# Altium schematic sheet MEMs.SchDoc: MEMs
size A4; Date: Not used; ApprovedBy: Not used; CheckedBy: Not used; Author: Not used; CompanyName: STMicroelectronics; DrawnBy: Not used; Engineer: Not used; Organization: Not used; Address1: Not used; Address2: Not used; Address3: Not used; Address4: Not used; DocumentNumber: 12; Revision: Not used; SheetNumber: 12; SheetTotal: 16
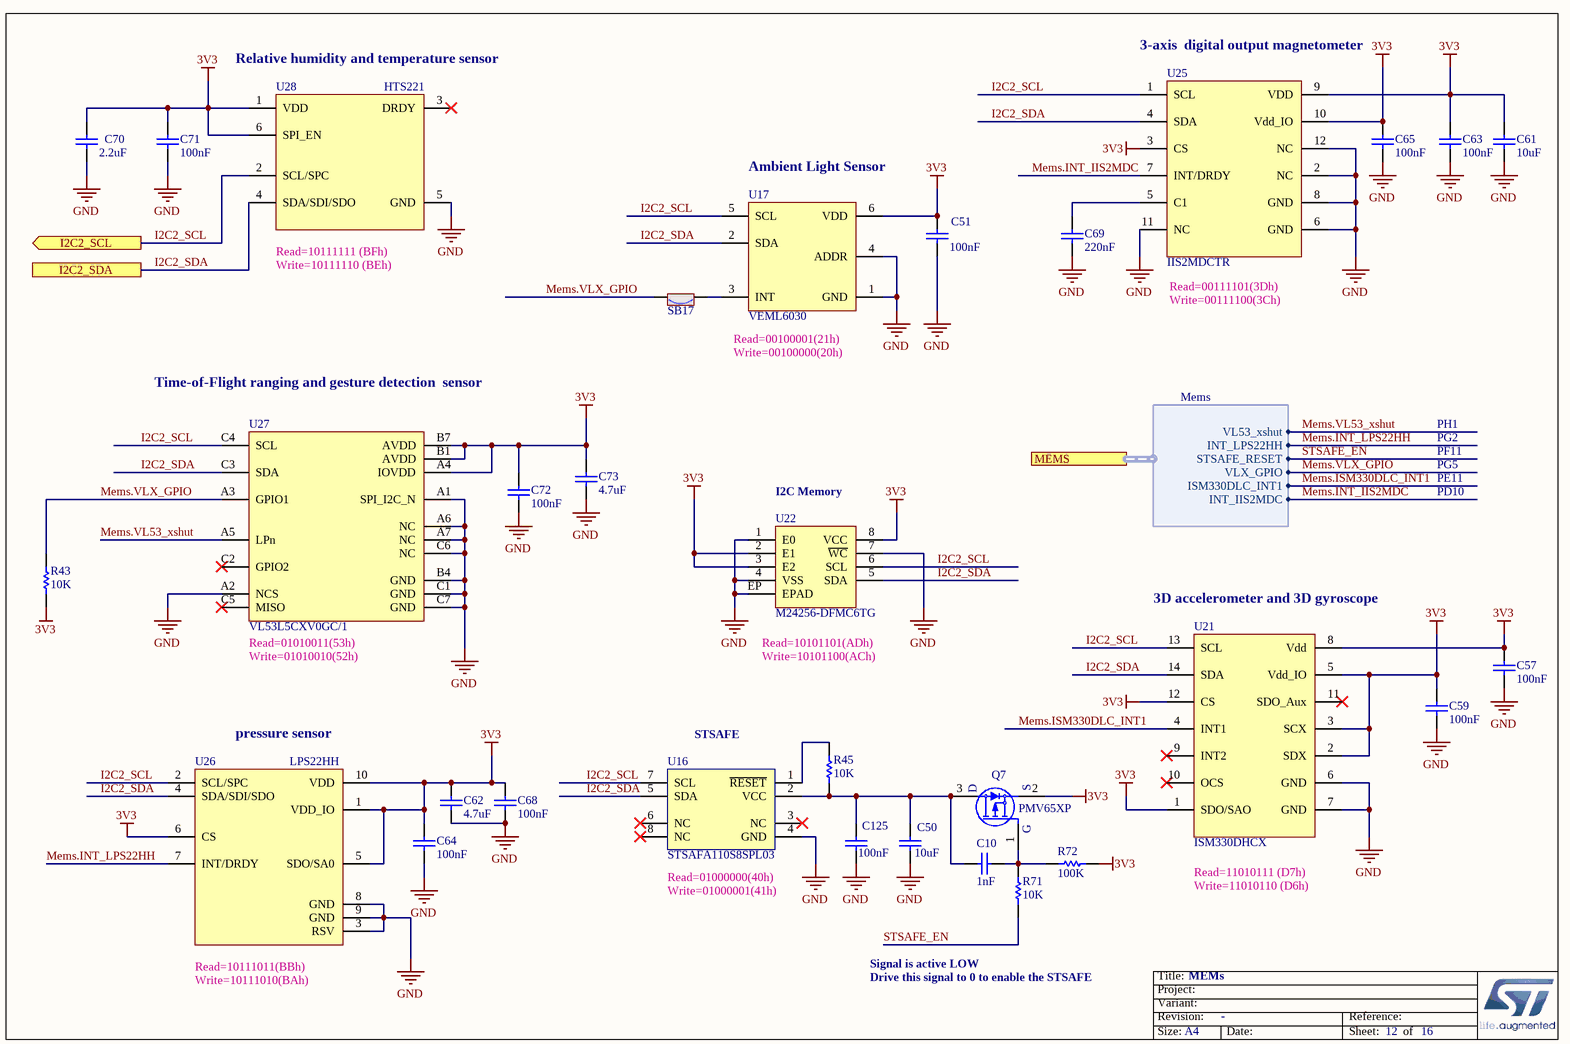
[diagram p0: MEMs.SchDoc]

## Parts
C10  value 1nF  [C0402]  (hidden comment: Capacitor)
C50  value 10uF  [C0402]  (hidden comment: Capacitor)
C51  value 100nF  [C0402]
C57  value 100nF  [C0402]
C59  value 100nF  [C0402]
C61  value 10uF  [C0603]  (hidden comment: Capacitor)
C62  value 4.7uF  [C0603]  (hidden comment: Capacitor)
C63  value 100nF  [C0402]
C64  value 100nF  [C0402]
C65  value 100nF  [C0402]
C68  value 100nF  [C0402]
C69  value 220nF  [C0402]  (hidden comment: Capacitor)
C70  value 2.2uF  [C0603_H0P8]  (hidden comment: Capacitor)
C71  value 100nF  [C0402]
C72  value 100nF  [C0402]
C73  value 4.7uF  [C0603]  (hidden comment: Capacitor)
C125  value 100nF  [C0402]
Q7  PMV65XP  [MOS_SOT23]
R43  value 10K  [R0402]  (hidden comment: Resistor)
R45  value 10K  [R0402]  (hidden comment: Resistor)
R71  value 10K  [R0402]  (hidden comment: Resistor)
R72  value 100K  [R0402]  (hidden comment: Resistor)
SB17  (no value)  [SOLDER-BRIDGE_R0603-0R]
U16  value STSAFA110S8SPL03  [ICC_SO8_5X4_P127]  (hidden comment: STSAFA110S8)
U17  VEML6030  [ICC_VISHAY_VEML6030_2X2_P065]
U21  ISM330DHCX  [ICC_LGA14_3X2P5_P050]
U22  value M24256-DFMC6TG  [ICC_DFN8-EPAD_2X3_P050]  (hidden comment: M24128-DFMC6TP)
U25  IIS2MDCTR  [ICC_LGA12_2X2_P050_H0P7]
U26  LPS22HH  [ICC_HLGA10_2X2_P050]
U27  value VL53L5CXV0GC/1  [ICC_LGA16_6P4X3_P075_H1P5]  (hidden comment: VL53L5CAV0GC)
U28  HTS221  [ICC_HLGA6_2X2_P075-1]

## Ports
I2C2_SCL (out), I2C2_SDA, MEMS (harness Mems)

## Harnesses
Mems: INT_LPS22HH, VLX_GPIO, ISM330DLC_INT1, INT_IIS2MDC, STSAFE_RESET, VL53_xshut

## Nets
3V3: C51.1 C57.1 C59.1 C61.2 C62.2 C63.1 C64.1 C65.1 C68.1 C70.2 C71.1 C72.1 C73.2 Q7.2(S) R43.2 R72.2 U17.6(VDD) U21.1(SDO/SAO) U21.2(SDX) U21.3(SCX) U21.5(Vdd_IO) U21.8(Vdd) U21.12(CS) U22.2(E1) U22.3(E2) U22.8(VCC) U25.3(CS) U25.9(VDD) U25.10(Vdd_IO) U26.1(VDD_IO) U26.5(SDO/SA0) U26.6(CS) U26.10(VDD) U27.A4(IOVDD) U27.B1(AVDD) U27.B7(AVDD) U28.1(VDD) U28.6(SPI_EN)
GND: C50.1 C51.2 C57.2 C59.2 C61.1 C62.1 C63.2 C64.2 C65.2 C68.2 C69.1 C70.1 C71.2 C72.2 C73.1 C125.2 U16.4(GND) U17.1(GND) U17.4(ADDR) U21.6(GND) U21.7(GND) U22.1(E0) U22.4(VSS) U22.7(~{WC}) U22.EP(EPAD) U25.2(NC) U25.6(GND) U25.8(GND) U25.11(NC) U25.12(NC) U26.3(RSV) U26.8(GND) U26.9(GND) U27.A1(SPI_I2C_N) U27.A2(NCS) U27.A6(NC) U27.A7(NC) U27.B4(GND) U27.C1(GND) U27.C6(NC) U27.C7(GND) U28.5(GND)
I2C2_SCL: U16.7(SCL) U17.5(SCL) U21.13(SCL) U22.6(SCL) U25.1(SCL) U26.2(SCL/SPC) U27.C4(SCL) U28.2(SCL/SPC) ; port I2C2_SCL
I2C2_SDA: U16.5(SDA) U17.2(SDA) U21.14(SDA) U22.5(SDA) U25.4(SDA) U26.4(SDA/SDI/SDO) U27.C3(SDA) U28.4(SDA/SDI/SDO) ; port I2C2_SDA
Mems.INT_IIS2MDC: U25.7(INT/DRDY) ; port MEMS.INT_IIS2MDC
Mems.INT_LPS22HH: U26.7(INT/DRDY) ; port MEMS.INT_LPS22HH
Mems.ISM330DLC_INT1: U21.4(INT1) ; port MEMS.ISM330DLC_INT1
Mems.VL53_xshut: U27.A5(LPn) ; port MEMS.VL53_xshut
Mems.VLX_GPIO: R43.1 SB17.2 U27.A3(GPIO1) ; port MEMS.VLX_GPIO
STSAFE_EN: R71.1 ; port MEMS.STSAFE_RESET
NetC10_1: C10.1 C50.2 C125.1 Q7.3(D) R45.1 U16.2(VCC)
NetC10_2: C10.2 Q7.1(G) R71.2 R72.1
NetC69_2: C69.2 U25.5(C1)
NetR45_2: R45.2 U16.1(~{RESET})
NetSB17_1: SB17.1 U17.3(INT)

Not connected (* = marked no-connect by the designer): U16 3(NC)* 6(NC)* 8(NC)*; U21 9(INT2)* 10(OCS)* 11(SDO_Aux)*; U27 C2(GPIO2)* C5(MISO)*; U28 3(DRDY)*

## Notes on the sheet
- (near U25) 3-axis  digital output magnetometer
- (near U28) Relative humidity and temperature sensor
- (near U17) Ambient Light Sensor
- (near U28) Read=10111111 (BFh)
  Write=10111110 (BEh)
- (near U25) Read=00111101(3Dh)
  Write=00111100(3Ch)
- Time-of-Flight ranging and gesture detection  sensor
- Read=00100001(21h)
  Write=00100000(20h)
- PG2
- PF11
- PH1
- (near U22) I2C Memory
- PE11
- PD10
- PG5
- (near U27) Read=01010011(53h)
  Write=01010010(52h)
- (near U22) Read=10101101(ADh)
  Write=10101100(ACh)
- (near U21) 3D accelerometer and 3D gyroscope
- (near U26) pressure sensor
- (near U16) STSAFE
- Read=01000000(40h)
  Write=01000001(41h)
- Read=11010111 (D7h)
  Write=11010110 (D6h)
- (near U26) Read=10111011(BBh)
  Write=10111010(BAh)
- Signal is active LOW
- Drive this signal to 0 to enable the STSAFE

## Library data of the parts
C10 = MCD-00198: Capacitor, MLCC, 1nF, 16V, X7R, +/-10%, 0402, T=0.5mm; Part_Preference: Recommended; Manufacturer: YAGEO; Manufacturer_Part_Number: CC0402KRX7R7BB102; Component_Country_Of_Origin: China; ShowFields: YES; ID: 2665
C50 = MCD-01716: Capacitor, MLCC, 10uF, 6V3, X5R, +/-20%, 0402, T=0.5mm; Part_Preference: Recommended; Manufacturer: YAGEO; Manufacturer_Part_Number: CC0402MRX5R5BB106
C51 C57 C59 C63-C65 C68 C71 C72 C125 = MCD-00006: Capacitor, MLCC, 100nF, 16V, X7R, 10%, 0402, T=0.5mm; Manufacturer_Part_Number: CC0402KRX7R7BB104; Manufacturer: YAGEO; Provided_By: Subcon; Initial_Board_Reference: MB1274
C61 = MCD-01124: Capacitor, MLCC, 10µF, 10V, X5R, 10%, 0603, T=0.8mm; Manufacturer_Part_Number: GRM188R61A106KAAL; Manufacturer: MURATA; Provided_By: SUBCO
C62 C73 = MCD-00009: Capacitor, MLCC, 4.7uF, 16V, X5R, 10%, 0603, T=0.8mm; Manufacturer_Part_Number: CC0603KRX5R7BB475; Manufacturer: YAGEO; Provided_By: subcon; Initial_Board_Reference: MB1274
C69 = MCD-00602: Capacitor, MLCC, 220nF, 16V, 0402, X7R, 10%, T=0,5mm; Manufacturer_Part_Number: GRM155R71C223KA01J; Manufacturer: MURATA; Provided_By: SUBCO
C70 = MCD-01540: Capacitor,X5R,2.2uF, 15%, 50V, 0603; Manufacturer_Part_Number: GRM188R61H225KE11; Manufacturer: MURATA; Provided_By: SUBCO
Q7 = MCD-01219: MOSFET, P-Channel , Vds: -20V, Id: -2.8A, Vgs(th): -0.9V, Vgs(max): +/-12V, Rdson:135mohm@Vgs=-1.8V, Qg=7.7nC; Part_Type: IC; Part_Preference: Recommended; Manufacturer: NXP; Component_Country_Of_Origin: China; ShowFields: YES; ID: 3277
R43 = MCD-00053: Resistor,10K,0402,1%,1/16W; Manufacturer_Part_Number: RC0402FR-0710KL; Manufacturer: YAGEO; Provided_By: SUBCO
R45 R71 = MCD-00053: Resistor, 10K, 0402, +/-1%, 1/16W; BMS_Part_Number: 9131590; Part_Preference: Recommended; Manufacturer: YAGEO; Manufacturer_Part_Number: RC0402FR-0710KL; Component_Country_Of_Origin: China; ShowFields: YES; ID: 2539
R72 = MCD-00059: Resistor, 100K, 0402, +/-1%, 1/16W; Part_Preference: Recommended; Manufacturer: YAGEO; Manufacturer_Part_Number: RC0402FR-07100KL; Component_Country_Of_Origin: China; ShowFields: YES; ID: 2533
SB17 = MCD-00071: Solder Bridge ON; Part_Type: Mechanical; Provided_By: Subcon; Initial_Board_Reference: mb1274
U16 = MCD-02399: Authentication, state-of-the-art security for peripherals and IoT devices; Part_Type: IC; Part_Preference: Recommended; Manufacturer: STMICROELECTRONICS; Component_Country_Of_Origin: Unknown; ShowFields: YES; ID: 4505
U17 = MCD-02336: High Accuracy Ambient Light Sensor with I2C Interface; Part_Type: IC; Part_Preference: Recommended; Manufacturer: VISHAY
U21 = MCD-02160: iNEMO inertial module: 3D accelerometer and 3D gyroscope, with digital output for industrial applications; Part_Preference: Recommended; Part_Type: IC; Manufacturer: STMICROELECTRONICS; Order_code_RS: ISM330DHCXTR; Component_Country_Of_Origin: Malta, Philippines
U22 = MCD-01871: I2C Memory 3V3, 256Kbits, 2x3,0.55mm, UFDFPN8; Part_Type: IC; Manufacturer: STMICROELECTRONICS; BMS_Part_Number: 9175665; Provided_By: SUBCO with ST control
U25 = MCD-01713: High-accuracy, ultra-low-power, 3-axis, digital output magnetometer; Part_Type: IC; Manufacturer: STMICROELECTRONICS; Provided_By: SUBCO with ST control
U26 = MCD-01702: High-performance MEMS nano pressure sensor:260-1260 hPa absolute digital output barometer; Part_Type: IC; Manufacturer: STMICROELECTRONICS; Provided_By: SUBCO
U27 = MCD-02257: Time-of-Flight mini depth camera; Part_Type: IC; Part_Preference: Recommended; Manufacturer: STMICROELECTRONICS; Manufacturer_HQ_COO: EU
U28 = MCD-01447: Capacitive digital sensor for relative humidity and temperature; Part_Type: IC; Manufacturer: STMICROELECTRONICS; BMS_Part_Number: 9188011; ECCN_US: EAR99; ECCN_EU: NEC; Provided_By: SUBCO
